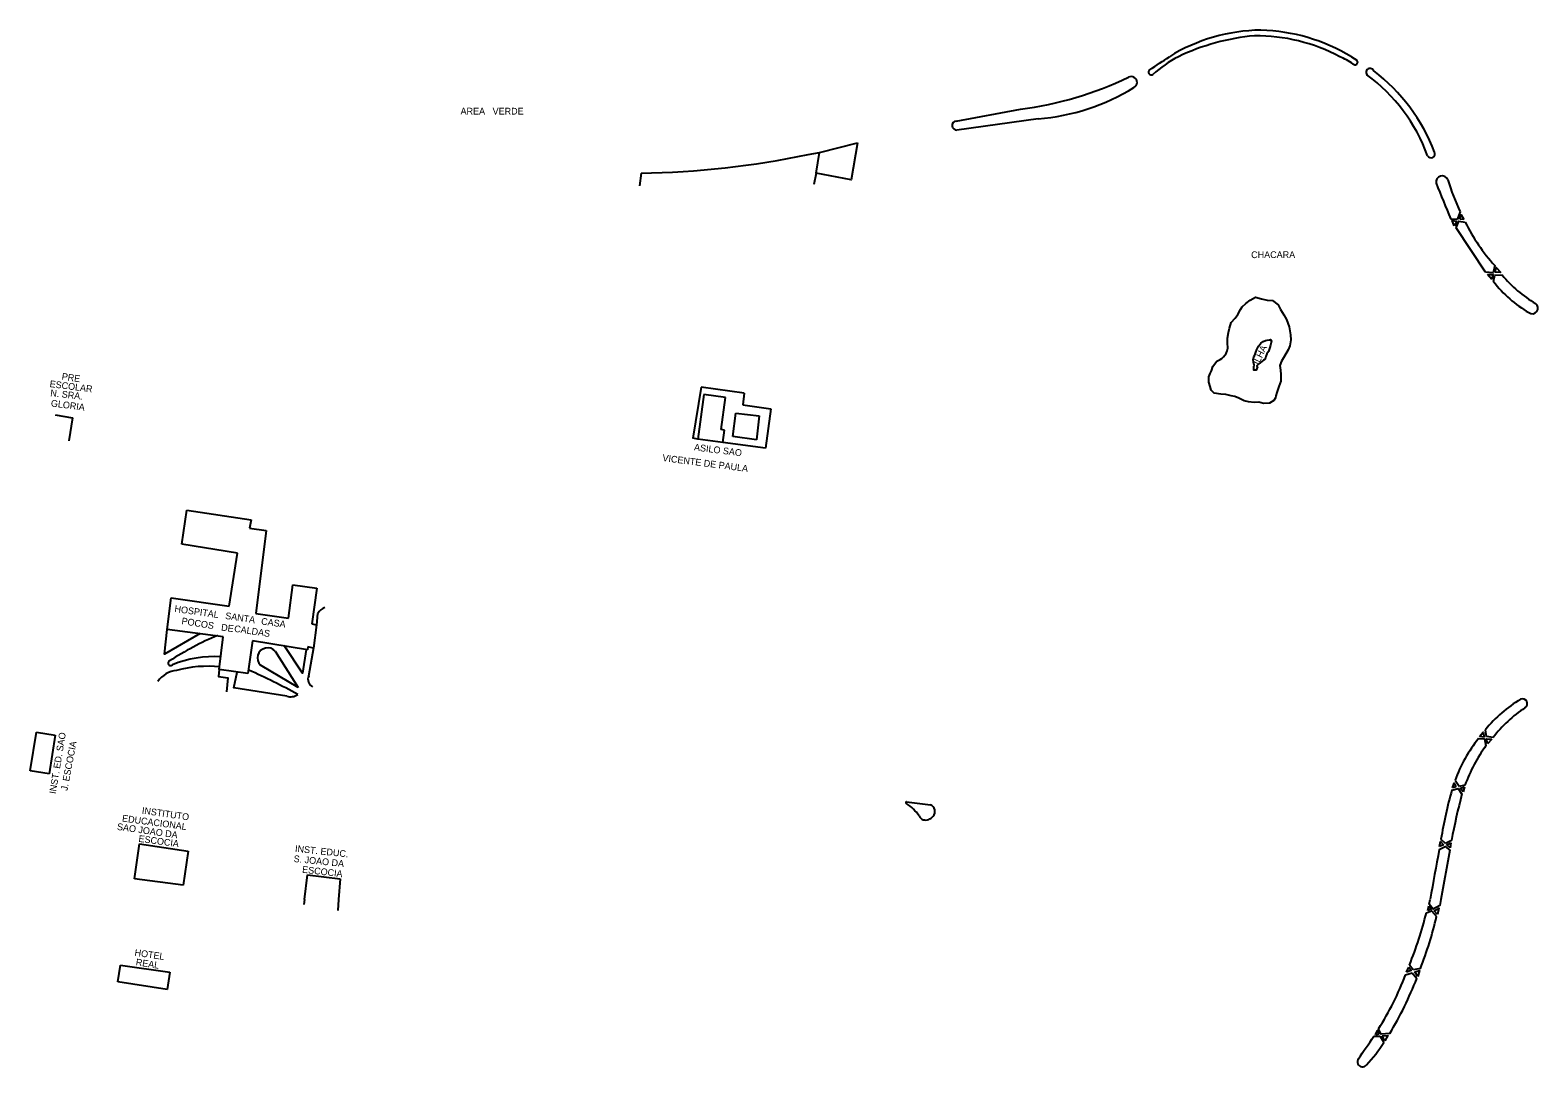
# Model space of a CAD drawing. Extents: x 325899 to 364828, y 7568995 to 7592502.
# Drawn here: x 338020 to 338915, y 7590403 to 7591018 of the extents above; entities that cross this region are included whole.
import ezdxf

# ---------------------------------------------------------------- set-up
doc = ezdxf.new("R2010")
doc.units = 0
for name, color, linetype in [('EDIFEXISTENT', 7, 'Continuous'), ('EDIFIDENTIF', 7, 'Continuous'), ('EDIFOBRAEXIS', 7, 'Continuous')]:
    doc.layers.add(name, color=color, linetype=linetype)

msp = doc.modelspace()

# ---------------------------------------------------------------- linework, layer by layer
at = {"layer": 'EDIFEXISTENT'}
for p, q in [((338417.96, 7590805.89), (338412.88, 7590775.47)), ((338419.55, 7590801.56), (338415.85, 7590775.04)), ((338443.45, 7590802.18), (338417.96, 7590805.89)), ((338432.42, 7590799.59), (338419.55, 7590801.56)), ((338443.45, 7590802.18), (338442.53, 7590795.4)), ((338429.76, 7590780.6), (338432.42, 7590799.59)), ((338442.53, 7590795.4), (338459.33, 7590793.03)), ((338459.33, 7590793.03), (338456.12, 7590769.59)), ((338034.46, 7590789.37), (338044.71, 7590787.67)), ((338044.71, 7590787.67), (338042.53, 7590774.03)), ((338436.62, 7590776.46), (338438.45, 7590790.36)), ((338438.45, 7590790.36), (338452.33, 7590788.79)), ((338452.33, 7590788.79), (338450.83, 7590774.55)), ((338415.85, 7590775.04), (338412.88, 7590775.47)), ((338430.83, 7590772.99), (338415.85, 7590775.04)), ((338431.79, 7590780.21), (338429.76, 7590780.6)), ((338430.83, 7590772.99), (338431.79, 7590780.21)), ((338450.83, 7590774.55), (338436.62, 7590776.46)), ((338456.12, 7590769.59), (338430.83, 7590772.99)), ((338109.68, 7590712.7), (338112.61, 7590732.81)), ((338112.61, 7590732.81), (338112.61, 7590732.81)), ((338112.61, 7590732.81), (338150.67, 7590727.07)), ((338150.67, 7590727.07), (338149.79, 7590722.23)), ((338149.79, 7590722.23), (338159.61, 7590720.68)), ((338142.61, 7590707.32), (338109.68, 7590712.7)), ((338159.61, 7590720.68), (338153.51, 7590671.51)), ((338137.73, 7590675.77), (338142.61, 7590707.32)), ((338173.01, 7590668.76), (338175.59, 7590688.59)), ((338175.59, 7590688.59), (338189.82, 7590686.6)), ((338189.82, 7590686.6), (338186.75, 7590665.32)), ((338100.9, 7590661.99), (338103.25, 7590680.73)), ((338103.25, 7590680.73), (338137.73, 7590675.77)), ((338153.51, 7590671.51), (338173.01, 7590668.76)), ((338134.23, 7590657.74), (338100.9, 7590661.99)), ((338186.75, 7590665.32), (338189.57, 7590664.73)), ((338189.57, 7590664.73), (338187.84, 7590650.98)), ((338131.8, 7590638.36), (338134.23, 7590657.74)), ((338151.47, 7590655.34), (338148.84, 7590635.82)), ((338184.24, 7590649.99), (338151.47, 7590655.34)), ((338184.33, 7590651.64), (338184.24, 7590649.99)), ((338187.84, 7590650.98), (338184.33, 7590651.64)), ((338148.84, 7590635.82), (338131.8, 7590638.36)), ((338019.56, 7590578.08), (338023.26, 7590601.14)), ((338023.26, 7590601.14), (338034.42, 7590599.34)), ((338034.42, 7590599.34), (338030.9, 7590576.33)), ((338030.9, 7590576.33), (338019.56, 7590578.08)), ((338081.52, 7590513.98), (338084.46, 7590534.89)), ((338084.46, 7590534.89), (338113.42, 7590530.42)), ((338113.42, 7590530.42), (338110.48, 7590510.22)), ((338182.43, 7590501.91), (338184.26, 7590516.42)), ((338184.26, 7590516.42), (338203.58, 7590514.14)), ((338110.48, 7590510.22), (338081.52, 7590513.98)), ((338203.58, 7590514.14), (338202.52, 7590501.91)), ((338182.43, 7590501.91), (338182.06, 7590498.8)), ((338202.52, 7590501.91), (338202.17, 7590495.26)), ((338071.56, 7590452.87), (338073.14, 7590462.85)), ((338073.14, 7590462.85), (338102.49, 7590458.7)), ((338100.96, 7590448.36), (338071.56, 7590452.87)), ((338102.49, 7590458.7), (338100.96, 7590448.36))]:
    msp.add_line(p, q, dxfattribs=at)
at = {"layer": 'EDIFOBRAEXIS'}
for points in [[(338803.89, 7591001.91), (338807.13, 7590999.79)], [(338569.25, 7590963.74), (338607.54, 7590970.73)], [(338617.96, 7590965.13), (338569.72, 7590958.36)], [(338481.39, 7590943.97), (338488.07, 7590945), (338510.6, 7590950.73), (338510.6, 7590950.73), (338510.6, 7590950.73)], [(338510.6, 7590950.73), (338506.92, 7590928.82), (338486.19, 7590932.86), (338484.84, 7590926.06)], [(338486.19, 7590932.86), (338488.07, 7590945)], [(338382.22, 7590932.88), (338381.28, 7590925.19)], [(338868.54, 7590909.76), (338866.74, 7590905.25)], [(338866.74, 7590905.25), (338862.91, 7590905.55)], [(338864.97, 7590901.63), (338863.78, 7590904.8), (338866.47, 7590904.31)], [(338866.47, 7590904.31), (338864.97, 7590901.63)], [(338866.1, 7590900.35), (338867.61, 7590904.22), (338871.5, 7590903.74)], [(338883.58, 7590873.97), (338866.1, 7590900.35)], [(338868.21, 7590905.47), (338869.11, 7590908.09), (338870.73, 7590905.21)], [(338870.73, 7590905.21), (338868.21, 7590905.47)], [(338889, 7590877.99), (338888.07, 7590873.75), (338883.58, 7590873.97)], [(338889.26, 7590874.01), (338889.85, 7590876.81), (338892.51, 7590873.91)], [(338892.51, 7590873.91), (338889.26, 7590874.01)], [(338884.68, 7590872.68), (338887.77, 7590872.71), (338887.21, 7590869.78)], [(338887.21, 7590869.78), (338884.68, 7590872.68)], [(338888.24, 7590868.42), (338889.02, 7590872.36), (338893.38, 7590872.44)], [(338730.15, 7590827.4), (338730.52, 7590829.03), (338730.34, 7590832.07), (338730.37, 7590834.96), (338730.88, 7590838.29), (338731.44, 7590840.83), (338732.58, 7590844.11), (338734.82, 7590846.69), (338736.53, 7590848.91), (338738.05, 7590851.94), (338739.13, 7590853.48), (338741.25, 7590855.45), (338743.8, 7590857.44), (338746.93, 7590859.27), (338750.59, 7590858.31), (338753.95, 7590857.37), (338757.09, 7590857.17), (338760.36, 7590854.73), (338761.73, 7590851.92), (338763.83, 7590848.69), (338765.32, 7590845.91), (338766.93, 7590841.61), (338767.75, 7590836.95), (338768.03, 7590833.93), (338767.25, 7590830.37), (338766.3, 7590827.93), (338764.12, 7590824.16), (338762.39, 7590821.28), (338761.4, 7590818.66), (338761.72, 7590815.94), (338761.97, 7590813.33), (338761.93, 7590809.3), (338760.86, 7590806.24), (338759.69, 7590802.71), (338759.02, 7590800.75), (338758.88, 7590799.56), (338757.75, 7590797.85), (338755.35, 7590796.36), (338751.68, 7590796.15), (338749.03, 7590796.87), (338746.22, 7590796.77), (338742.89, 7590797.18), (338740.3, 7590797.76), (338737.11, 7590799.29), (338734.64, 7590800.26), (338732.43, 7590800.7), (338729.41, 7590801.39), (338726.36, 7590801.74), (338722.35, 7590802.24), (338720.74, 7590803.98), (338720.06, 7590806.13), (338719.25, 7590808.84), (338719.26, 7590810.54), (338719.25, 7590811.99), (338720, 7590813.85), (338720.75, 7590815.6), (338721.67, 7590818.05), (338723.15, 7590820.34), (338724.08, 7590821.24), (338726.03, 7590822.29), (338726.99, 7590822.83), (338727.97, 7590823.88), (338729.6, 7590825.87), (338730.15, 7590827.4)], [(338746.03, 7590817.88), (338746.15, 7590818.95), (338745.78, 7590820.64), (338745.64, 7590822.21), (338745.91, 7590823.74), (338746.48, 7590824.86), (338747.2, 7590826.54), (338747.67, 7590828.09), (338748.7, 7590830.05), (338749.78, 7590831.38), (338750.21, 7590832.02), (338751.49, 7590832.92), (338752.91, 7590833.49), (338753.87, 7590833.72), (338755.24, 7590833.83), (338755.82, 7590834.09), (338756.42, 7590833.08), (338755.9, 7590830.67), (338755.53, 7590829.32), (338754.69, 7590827.05), (338753.78, 7590825.52), (338753.16, 7590824), (338752.61, 7590822.5), (338751.71, 7590821.88), (338749.76, 7590820.29), (338748.86, 7590819.68), (338747.7, 7590818.48), (338748.06, 7590817.89), (338747.29, 7590815.99), (338746.55, 7590815.98), (338745.97, 7590815.98), (338746.03, 7590817.88)], [(338189.73, 7590664.53), (338190.39, 7590671.55)], [(338120.58, 7590659.67), (338099.25, 7590647.4), (338100.9, 7590661.99)], [(338183.46, 7590650.21), (338181.27, 7590636.02), (338170.31, 7590652.56)], [(338184.94, 7590634.53), (338187.92, 7590651.31)], [(338178.71, 7590627.68), (338156.27, 7590640.85)], [(338165.02, 7590649.12), (338178.71, 7590627.68)], [(338131.8, 7590638.36), (338131.45, 7590634.2), (338136.99, 7590633.27), (338136.04, 7590625.11)], [(338171.87, 7590622.55), (338140.44, 7590627.33), (338142.46, 7590636.69)], [(338879.41, 7590597.29), (338882.98, 7590597.22), (338883.78, 7590593.11)], [(338880.03, 7590598.57), (338882.19, 7590601.2), (338882.62, 7590598.18)], [(338882.62, 7590598.18), (338880.03, 7590598.57)], [(338884.12, 7590598.45), (338883.4, 7590602.58)], [(338887.95, 7590597.94), (338884.12, 7590598.45)], [(338884.68, 7590594.24), (338884.15, 7590597.15), (338887.17, 7590597.02)], [(338887.17, 7590597.02), (338884.68, 7590594.24)], [(338863.9, 7590567.99), (338864.87, 7590570.92), (338865.95, 7590568.59)], [(338867.83, 7590568.79), (338865.49, 7590572.52)], [(338871.3, 7590569.7), (338867.83, 7590568.79)], [(338870.16, 7590565.71), (338868.59, 7590567.88), (338871.05, 7590568.71)], [(338871.05, 7590568.71), (338870.16, 7590565.71)], [(338539.85, 7590559.72), (338553.99, 7590557.98)], [(338863.55, 7590566.75), (338867.2, 7590567.74), (338869.51, 7590564.41)], [(338865.95, 7590568.59), (338863.9, 7590567.99)], [(338856.04, 7590531.42), (338859.55, 7590533.17), (338862.23, 7590531.01), (338857.05, 7590501.91)], [(338856.22, 7590533.33), (338856.84, 7590536.27), (338858.55, 7590534.26)], [(338858.55, 7590534.26), (338856.22, 7590533.33)], [(338859.79, 7590535.13), (338857.05, 7590537.55)], [(338863.33, 7590536.88), (338859.79, 7590535.13)], [(338862.47, 7590532.51), (338860.45, 7590534.17), (338862.88, 7590535.38)], [(338862.88, 7590535.38), (338862.47, 7590532.51)], [(338849.82, 7590498.08), (338851.2, 7590496), (338849.2, 7590495.36)], [(338849.2, 7590495.36), (338849.82, 7590498.08)], [(338857.05, 7590501.91), (338856.37, 7590498.2), (338852.51, 7590496.1), (338850.12, 7590499.14), (338850.7, 7590501.91)], [(338848.4, 7590493.85), (338851.47, 7590495.08), (338854.41, 7590491.66)], [(338853.1, 7590495.16), (338855.75, 7590496.64), (338854.91, 7590492.89)], [(338854.91, 7590492.89), (338853.1, 7590495.16)], [(338837.91, 7590461.61), (338839.34, 7590459.61), (338836.65, 7590458.76)], [(338836.65, 7590458.76), (338837.91, 7590461.61)], [(338840.61, 7590460.04), (338838.34, 7590462.93)], [(338835.94, 7590457.11), (338839.95, 7590458.37)], [(338839.95, 7590458.37), (338842.68, 7590454.97)], [(338844.82, 7590460.8), (338840.61, 7590460.04)], [(338841.45, 7590458.83), (338844.32, 7590459.68), (338843.26, 7590456.14)], [(338843.26, 7590456.14), (338841.45, 7590458.83)], [(338817.24, 7590420.65), (338820.89, 7590420.69)], [(338818.17, 7590421.59), (338819.31, 7590424.13), (338820.1, 7590421.9)], [(338820.1, 7590421.9), (338818.17, 7590421.59)], [(338826.63, 7590422.26), (338821.65, 7590421.88), (338819.94, 7590425.07)], [(338820.89, 7590420.69), (338823.07, 7590416.99)], [(338822.11, 7590420.97), (338825.54, 7590421.06), (338823.65, 7590418)], [(338823.65, 7590418), (338822.11, 7590420.97)]]:
    msp.add_lwpolyline(points, dxfattribs=at)
for centre, radius, start, end in [((338751.09, 7590912.9), 104.75, 90.47552, 121.81613), ((338747.08, 7590907.56), 110.14, 58.95038, 88.36819), ((338758.24, 7590882.24), 132.59, 95.11468, 115.50229), ((338747.21, 7590908.1), 106.2, 62.04408, 90.42312), ((338198.63, 7591731.16), 882.64, 303.37758, 304.2881), ((338737.63, 7590932.87), 78.08, 117.84291, 131.42439), ((338777.04, 7590955.46), 50.56, 56.65008, 66.75168), ((338806.06, 7590998.65), 1.56, 218.06702, 46.85573), ((338579.52, 7591182.87), 213.98, 277.52206, 295.4748), ((338673.22, 7590986.67), 3.44, 297.84329, 118.8081), ((338685.03, 7590992.73), 1.6, 120.84441, 305.44776), ((338815.02, 7590992.54), 2.39, 21.5561, 216.83693), ((338752.18, 7590907.81), 103.2, 20.00867, 53.81537), ((338750.76, 7590906.21), 109.67, 20.88699, 52.67642), ((338608.79, 7591089.96), 125.17, 274.19946, 301.8427), ((338569.56, 7590961.06), 2.7, 96.58002, 273.46809), ((338851.18, 7590944.22), 2.31, 208.43234, 28.11011), ((338376.15, 7591435.96), 503.12, 270.69195, 282.07443), ((338857.71, 7590927.61), 3.57, 20.43439, 192.27913), ((339464.86, 7591163.55), 654.91, 201.18764, 203.20008), ((339023.8, 7590981.57), 171.07, 197.94838, 204.82225), ((338972.31, 7590953.45), 112.4, 206.24695, 222.16739), ((338948.57, 7590916.08), 76.89, 218.30395, 239.21236), ((338951.65, 7590920.34), 75.43, 219.42158, 239.39894), ((338911.2, 7590852.75), 3.37, 233.93104, 52.45574), ((338196.66, 7590668.16), 7.13, 106.97743, 151.66422), ((338201.38, 7590490.88), 181.86, 112.78589, 123.01036), ((338160.51, 7590645.12), 6.02, 41.52917, 225.18652), ((338102.94, 7590642.08), 1.45, 116.02352, 315.27926), ((338128.92, 7590579.96), 65.99, 86.5503, 112.21366), ((338107.79, 7590622.85), 14.94, 95.12799, 146.02409), ((338124.79, 7590570.71), 69.48, 83.85938, 105.29903), ((337971.99, 7590244.4), 431.66, 61.43137, 65.73528), ((338189.5, 7590632.43), 5.02, 155.27593, 242.01248), ((338174.28, 7590628.87), 6.77, 249.0935, 307.61215), ((338947.84, 7590549.23), 83.65, 121.34658, 140.3814), ((338951.65, 7590548.31), 80.75, 123.63557, 142.07778), ((338905.45, 7590618.02), 2.88, 300.66634, 113.11653), ((338943.46, 7590545.01), 82.69, 140.77654, 160.56171), ((338965.13, 7590534.71), 100.14, 144.32569, 159.55082), ((338539.77, 7590559.27), 0.46, 80.07655, 271.27495), ((339103.48, 7590498.02), 249.57, 164.01578, 170.88834), ((339236.07, 7590467.62), 379.13, 165.2082, 169.47279), ((338521.98, 7590533.01), 31.35, 36.06152, 55.40292), ((338550.83, 7590552.69), 3.72, 199.40403, 251.47476), ((338551.11, 7590554.59), 5.61, 254.84111, 323.77568), ((338552.4, 7590554.03), 4.26, 319.55008, 68.07473), ((340239.47, 7590266.13), 1408.64, 169.14464, 170.3644), ((338617.99, 7590551.78), 237.59, 338.03875, 345.8863), ((338640.91, 7590541.05), 219.13, 338.51761, 346.97578), ((338681.9, 7590514.07), 164.24, 327.19001, 339.70714), ((338643.88, 7590532.23), 213.29, 328.96165, 338.76379), ((338289.05, 7590776.22), 636.72, 324.59762, 326.0519), ((338757.6, 7590457.21), 76.83, 315.95499, 328.43166), ((338810.39, 7590405.51), 2.99, 141.70422, 324.98302)]:
    msp.add_arc(centre, radius, start, end, dxfattribs=at)

# ---------------------------------------------------------------- texts
at = {"layer": 'EDIFIDENTIF'}
for s, rotation, p in [('AREA   VERDE', 359.94901, (338275.05, 7590967.61)), ('CHACARA', 0.11301, (338744.37, 7590882.39)), ('ILHA', 64.32134, (338748.82, 7590818.79)), ('PRE', 351.48754, (338038.1, 7590810.35)), ('ESCOLAR', 352.71249, (338030.96, 7590805.91)), ('N. SRA.', 353.69952, (338031.37, 7590800.49)), ('GLORIA', 352.8107, (338031.69, 7590794.41)), ('VICENTE DE PAULA', 352.74849, (338394.74, 7590761.96)), ('ASILO SAO', 352.82242, (338413.49, 7590768.34)), ('HOSPITAL', 352.02196, (338105.06, 7590672.47)), ('POCOS', 350.97918, (338109.21, 7590665.25)), ('SANTA', 351.47876, (338135.18, 7590668.33)), ('CASA', 352.50428, (338156.51, 7590665.02)), ('DE', 352.42178, (338132.76, 7590661.46)), ('CALDAS', 351.55074, (338140.48, 7590660.69)), ('INST. ED. SAO', 80.51832, (338034.75, 7590564.26)), ('J. ESCOCIA', 79.29631, (338041.66, 7590566.13)), ('EDUCACIONAL', 352.3878, (338073.95, 7590548.12)), ('INSTITUTO', 351.7272, (338085.68, 7590552.76)), ('SAO JOAO DA', 351.87212, (338070.94, 7590543.17)), ('ESCOCIA', 352.40834, (338083.72, 7590536.05)), ('INST. EDUC.', 353.95054, (338176.65, 7590530.15)), ('S. JOAO DA', 354.18168, (338175.83, 7590524.12)), ('ESCOCIA', 353.48214, (338180.87, 7590517.74)), ('HOTEL', 351.66976, (338081.35, 7590468.47)), ('REAL', 351.329, (338082.06, 7590462.8))]:
    msp.add_text(s, height=4, rotation=rotation, dxfattribs=at).set_placement(p)

doc.saveas('drawing.dxf')
